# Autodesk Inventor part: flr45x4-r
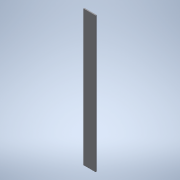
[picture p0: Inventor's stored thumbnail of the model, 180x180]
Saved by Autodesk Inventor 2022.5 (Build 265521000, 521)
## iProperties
Created: 2016-12
Part Number: flr45x4-r
Material: 一般
Document SubType Name: Modeling
Designer: imaocorp
Density: 1 g/cm^3
Appearance: 既定
Author: imaocorp
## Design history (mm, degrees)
node "flr45x4-r.x_t1"
node "flr45x4-r"
node "Base1"
